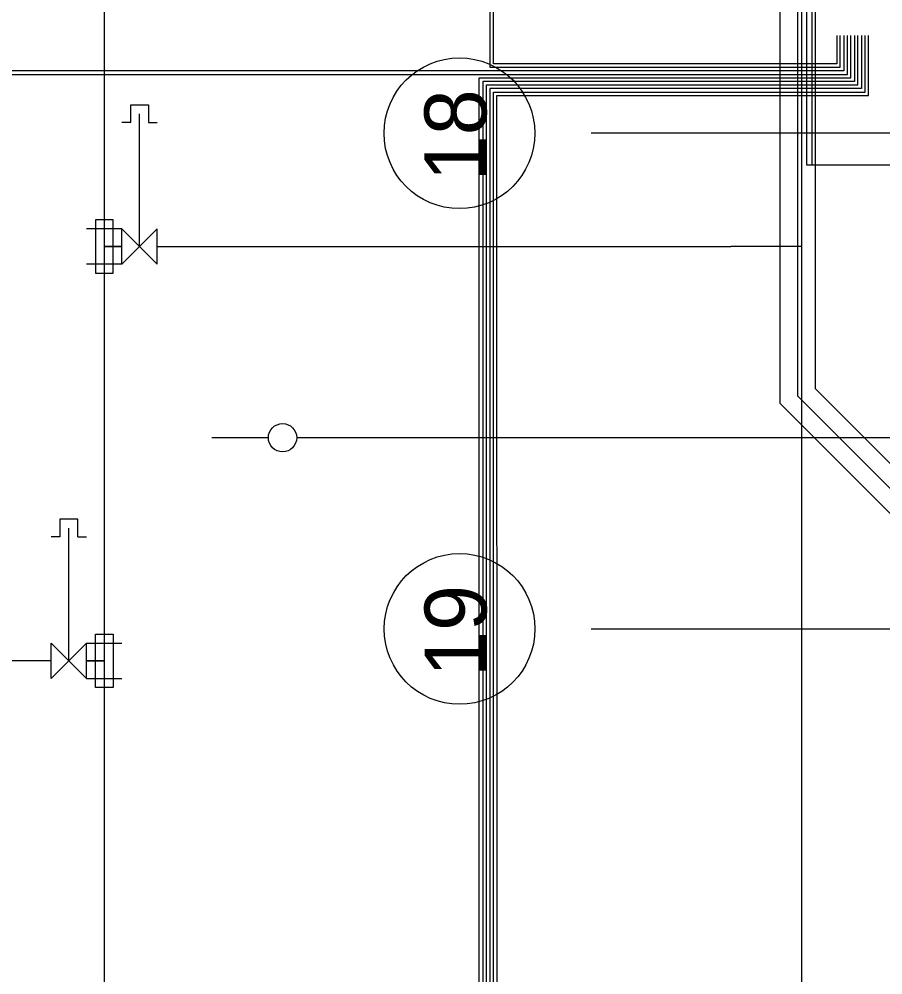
# Model space of a CAD drawing. Extents: x -264222 to -263592, y -1242345 to -1242048.
# Drawn here: x -263925.35 to -263913.14, y -1242207.77 to -1242194.27 of the extents above; entities that cross this region are included whole.
import ezdxf

# ---------------------------------------------------------------- set-up
doc = ezdxf.new("R2010")
doc.units = 0
for name, color, linetype in [('HESCON_OSI_STAVBY_KFA', 7, 'Continuous'), ('KFA_2D_SITUACIA_DSP', 7, 'Continuous'), ('KFA_SO_62-1_VO_TRASA_KABLOV_PROJEKT', 7, 'Continuous')]:
    doc.layers.add(name, color=color, linetype=linetype)

msp = doc.modelspace()

# ---------------------------------------------------------------- linework, layer by layer
at = {"layer": 'HESCON_OSI_STAVBY_KFA'}
for p, q in [((-263792.653, -1242195.882), (-263917.263, -1242195.882)), ((-263917.265, -1242202.882), (-263905.505, -1242202.882)), ((-263917.265, -1242202.882), (-263905.505, -1242202.882))]:
    msp.add_line(p, q, dxfattribs=at)
for centre in [(-263919.125, -1242195.882), (-263919.123, -1242202.882)]:
    msp.add_circle(centre, 1.064, dxfattribs=at)
at = {"layer": 'KFA_2D_SITUACIA_DSP'}
for p, q in [((-263914.218, -1242196.332), (-263914.218, -1242132.432)), ((-263924.143, -1242185.14), (-263924.143, -1242250.14)), ((-263923.768, -1242195.732), (-263923.768, -1242195.482)), ((-263923.768, -1242195.482), (-263923.518, -1242195.482)), ((-263923.518, -1242195.482), (-263923.518, -1242195.732)), ((-263923.643, -1242197.482), (-263923.643, -1242195.607)), ((-263923.768, -1242195.732), (-263923.893, -1242195.732)), ((-263923.518, -1242195.732), (-263923.393, -1242195.732)), ((-263909.118, -1242196.332), (-263914.218, -1242196.332)), ((-263924.018, -1242197.107), (-263924.268, -1242197.107)), ((-263924.268, -1242197.107), (-263924.268, -1242197.857)), ((-263924.018, -1242197.857), (-263924.018, -1242197.107)), ((-263923.893, -1242197.232), (-263924.393, -1242197.232)), ((-263923.893, -1242197.732), (-263923.893, -1242197.232)), ((-263923.893, -1242197.232), (-263923.393, -1242197.732)), ((-263923.393, -1242197.232), (-263923.893, -1242197.732)), ((-263923.393, -1242197.732), (-263923.393, -1242197.232)), ((-263924.143, -1242197.482), (-263923.893, -1242197.482)), ((-263923.893, -1242197.482), (-263924.143, -1242197.482)), ((-263923.393, -1242197.482), (-263915.293, -1242197.482)), ((-263914.293, -1242197.482), (-263915.293, -1242197.482)), ((-263923.893, -1242197.732), (-263924.393, -1242197.732)), ((-263924.268, -1242197.857), (-263924.018, -1242197.857)), ((-263921.824, -1242200.182), (-263922.624, -1242200.182)), ((-263915.293, -1242200.182), (-263921.424, -1242200.182)), ((-263909.043, -1242200.182), (-263915.293, -1242200.182)), ((-263924.768, -1242201.332), (-263924.768, -1242201.582)), ((-263924.518, -1242201.332), (-263924.768, -1242201.332)), ((-263924.518, -1242201.582), (-263924.518, -1242201.332)), ((-263924.768, -1242201.582), (-263924.893, -1242201.582)), ((-263924.643, -1242203.332), (-263924.643, -1242201.457)), ((-263924.518, -1242201.582), (-263924.393, -1242201.582)), ((-263924.268, -1242203.707), (-263924.268, -1242202.957)), ((-263924.268, -1242202.957), (-263924.018, -1242202.957)), ((-263924.018, -1242202.957), (-263924.018, -1242203.707)), ((-263924.893, -1242203.582), (-263924.893, -1242203.082)), ((-263924.393, -1242203.082), (-263924.893, -1242203.582)), ((-263924.893, -1242203.082), (-263924.393, -1242203.582)), ((-263924.393, -1242203.582), (-263924.393, -1242203.082)), ((-263924.393, -1242203.082), (-263923.893, -1242203.082)), ((-263924.893, -1242203.332), (-263958.097, -1242203.332)), ((-263924.143, -1242203.332), (-263924.393, -1242203.332)), ((-263924.393, -1242203.332), (-263924.143, -1242203.332)), ((-263924.393, -1242203.582), (-263923.893, -1242203.582)), ((-263924.018, -1242203.707), (-263924.268, -1242203.707))]:
    msp.add_line(p, q, dxfattribs=at)
for points in [[(-263794.893, -1242227.382), (-263808.968, -1242241.457), (-263894.968, -1242241.457), (-263909.043, -1242227.382), (-263909.043, -1242196.333), (-263914.143, -1242196.333), (-263914.143, -1242132.433), (-263909.043, -1242132.433), (-263909.043, -1242101.382), (-263894.968, -1242087.307), (-263808.968, -1242087.307), (-263794.893, -1242101.382), (-263794.893, -1242227.382)], [(-263918.489, -1242164.132), (-263914.1, -1242168.521), (-263914.1, -1242199.486), (-263910.004, -1242203.582), (-263891.768, -1242203.582)], [(-263918.593, -1242164.382), (-263914.35, -1242168.625), (-263914.35, -1242199.59), (-263910.108, -1242203.832), (-263891.768, -1242203.832)], [(-263918.696, -1242164.632), (-263914.6, -1242168.728), (-263914.6, -1242199.693), (-263910.211, -1242204.082), (-263891.768, -1242204.082)]]:
    msp.add_lwpolyline(points, dxfattribs=at)
msp.add_lwpolyline([(-263893.618, -1242118.282), (-263916.093, -1242118.282), (-263916.093, -1242175.482), (-263914.293, -1242175.482), (-263914.293, -1242210.482), (-263893.618, -1242210.482), (-263893.618, -1242166.382), (-263900.043, -1242166.382), (-263900.043, -1242162.382), (-263893.618, -1242162.382)], close=True, dxfattribs=at)
msp.add_circle((-263921.624, -1242200.182), 0.2, dxfattribs=at)
at = {"layer": 'KFA_SO_62-1_VO_TRASA_KABLOV_PROJEKT'}
for p, q in [((-263918.645, -1242194.9), (-263918.645, -1242084.831)), ((-263918.695, -1242110.308), (-263918.695, -1242194.95)), ((-263913.795, -1242194.5), (-263913.795, -1242194.9)), ((-263913.745, -1242194.95), (-263913.745, -1242194.5)), ((-263913.695, -1242194.5), (-263913.695, -1242195)), ((-263913.645, -1242195.05), (-263913.645, -1242194.5)), ((-263913.595, -1242195.1), (-263913.595, -1242194.5)), ((-263913.545, -1242194.5), (-263913.545, -1242195.15)), ((-263913.495, -1242195.2), (-263913.495, -1242194.5)), ((-263913.445, -1242194.5), (-263913.445, -1242195.25)), ((-263913.395, -1242195.3), (-263913.395, -1242194.5)), ((-263913.345, -1242195.35), (-263913.345, -1242194.5)), ((-263918.695, -1242194.95), (-263913.745, -1242194.95)), ((-263913.795, -1242194.9), (-263918.645, -1242194.9)), ((-263948.745, -1242195.05), (-263913.645, -1242195.05)), ((-263913.695, -1242195), (-263948.695, -1242195)), ((-263918.845, -1242300.4), (-263918.845, -1242195.1)), ((-263918.845, -1242195.1), (-263913.595, -1242195.1)), ((-263913.545, -1242195.15), (-263918.795, -1242195.15)), ((-263918.795, -1242195.15), (-263918.795, -1242300.4)), ((-263918.745, -1242268.464), (-263918.745, -1242195.2)), ((-263918.745, -1242195.2), (-263913.495, -1242195.2)), ((-263913.445, -1242195.25), (-263918.695, -1242195.25)), ((-263918.695, -1242195.25), (-263918.695, -1242268.464)), ((-263918.638, -1242250.863), (-263918.645, -1242195.3)), ((-263918.645, -1242195.3), (-263913.395, -1242195.3)), ((-263918.593, -1242217.248), (-263918.595, -1242195.35)), ((-263918.595, -1242195.35), (-263913.345, -1242195.35))]:
    msp.add_line(p, q, dxfattribs=at)

# ---------------------------------------------------------------- texts
at = {"layer": 'HESCON_OSI_STAVBY_KFA'}
for s, p in [('18', (-263918.744, -1242196.562)), ('19', (-263918.742, -1242203.562))]:
    msp.add_text(s, height=0.875, rotation=90, dxfattribs=at).set_placement(p)

doc.saveas('drawing.dxf')
